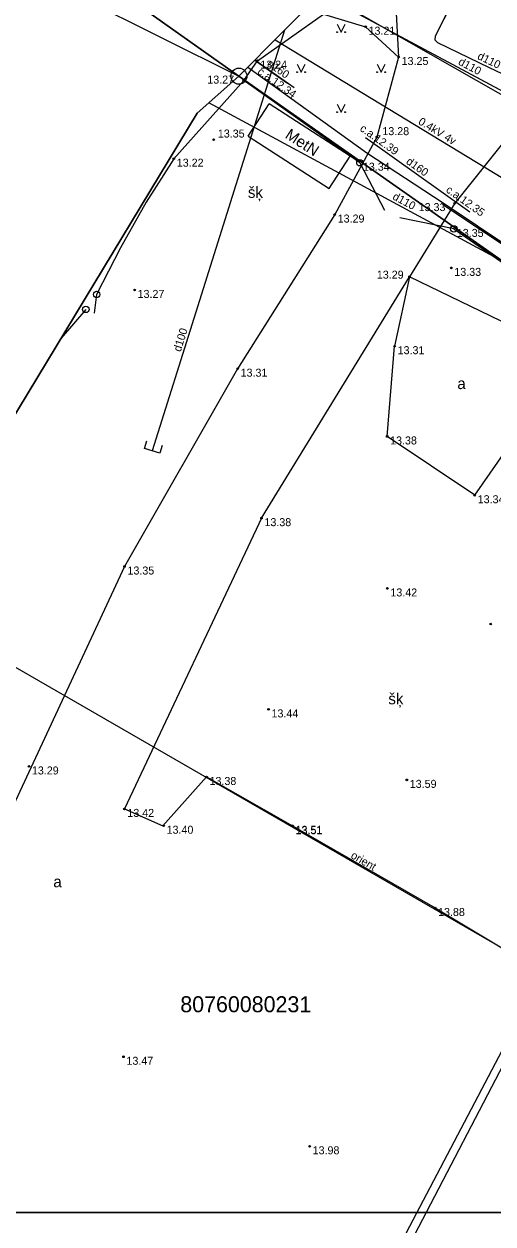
# Model space of a CAD drawing. Extents: x 503904 to 504094, y 304688 to 304960.
# Drawn here: x 503967.7 to 503997, y 304823 to 304898 of the extents above; entities that cross this region are included whole.
import ezdxf

# ---------------------------------------------------------------- set-up
doc = ezdxf.new("R2010")
doc.units = 0
for name, color, linetype in [('APGR_ELEM_####_####_#', 7, 'Continuous'), ('APGR_SARK_####_####_#', 7, 'Continuous'), ('APGS_ACRL_####_####_#', 7, 'Continuous'), ('APGS_ACRL_####_TKST_#', 7, 'Continuous'), ('APGS_VADP_ZSPR_####_#', 7, 'Continuous'), ('BUVE_EKAS_####_####_#', 7, 'Continuous'), ('BUVE_EKAS_BPAL_####_#', 7, 'Continuous'), ('BUVE_EKAS_RAKS_TKST_#', 7, 'Continuous'), ('CELI_CMAL_####_####_#', 7, 'Continuous'), ('CELI_CSEG_####_TKST_#', 7, 'Continuous'), ('CELI_TAKA_####_####_#', 7, 'Continuous'), ('ELEK_ACRL_####_####_#', 7, 'Continuous'), ('ELEK_ACRL_####_TKST_#', 7, 'Continuous'), ('ELEK_VADP_VSPR_####_#', 7, 'Continuous'), ('ELEK_VADP_VSPR_####_I', 7, 'Continuous'), ('ELEK_VADP_ZSPR_####_#', 7, 'Continuous'), ('ELEK_VADV_ZSPR_####_#', 7, 'Continuous'), ('ELEK_VADV_ZSPR_TKST_#', 7, 'Continuous'), ('NORB_ELEM_####_####_#', 7, 'Continuous'), ('NORB_ZOGS_BARJ_####_#', 7, 'Continuous'), ('NORB_ZOGS_ZSTP_####_#', 7, 'Continuous'), ('RAMI_PLAN_####_TKST_#', 7, 'Continuous'), ('RAMI_UZMR_####_####_#', 7, 'Continuous'), ('RELJ_AATZ_####_TKST_#', 7, 'Continuous'), ('RELJ_ELEM_####_####_#', 7, 'Continuous'), ('ROBZ_UZMR_####_####_#', 7, 'Continuous'), ('ROBZ_UZMR_####_TKST_#', 7, 'Continuous'), ('SAKK_KKAN_####_####_#', 7, 'Continuous'), ('SAKT_VADP_KABE_####_#', 7, 'Continuous'), ('SAKT_VADP_KABE_TKST_#', 7, 'Continuous'), ('TERT_ELEM_####_####_#', 7, 'Continuous'), ('UDTK_ELEM_####_####_#', 7, 'Continuous'), ('UDTK_VADP_NEDR_####_#', 7, 'Continuous'), ('UDTK_VADP_NEDR_TKST_#', 7, 'Continuous'), ('UDTK_VADP_UDEN_####_#', 7, 'Continuous'), ('UDTK_VADP_UDEN_TKST_#', 7, 'Continuous')]:
    doc.layers.add(name, color=color, linetype=linetype)

msp = doc.modelspace()

# ---------------------------------------------------------------- linework, layer by layer
at = {"layer": 'APGR_ELEM_####_####_#'}
msp.add_circle((503981.12, 304894.75), 0.5, dxfattribs=at)
at = {"layer": 'APGR_SARK_####_####_#'}
for p, q in [((503967.818, 304901.39), (503981.123, 304894.75)), ((503981.123, 304894.75), (504030.463, 304860.121))]:
    msp.add_line(p, q, dxfattribs=at)
at = {"layer": 'APGS_ACRL_####_####_#'}
msp.add_lwpolyline([(503997.708, 304905.8), (503994.46, 304899.393), (503993.378, 304897.257), (503993.361, 304897.025), (503993.516, 304896.851), (503996.758, 304895.298), (503998.379, 304894.525), (504000, 304893.745), (504003.241, 304892.193)], dxfattribs=at)
at = {"layer": 'APGS_VADP_ZSPR_####_#'}
msp.add_lwpolyline([(503994.396, 304908.162), (503998.01, 304906.396), (503995.543, 304901.529), (503993.378, 304897.257), (503993.361, 304897.025), (503993.516, 304896.85), (503996.758, 304895.3), (504000, 304893.749), (504004.081, 304891.797), (504008.162, 304889.845), (504008.322, 304889.653), (504008.281, 304889.406), (504007.328, 304888.005), (504006.375, 304886.604), (504006.058, 304885.968)], dxfattribs=at)
at = {"layer": 'BUVE_EKAS_####_####_#'}
msp.add_line((504000.528, 304838.553), (503966.985, 304774.25), dxfattribs=at)
at = {"layer": 'BUVE_EKAS_BPAL_####_#'}
for p, q in [((503981.706, 304891.005), (503983.013, 304893.018)), ((503988.061, 304889.741), (503983.013, 304893.018)), ((503981.706, 304891.005), (503986.754, 304887.728)), ((503986.754, 304887.728), (503988.061, 304889.741))]:
    msp.add_line(p, q, dxfattribs=at)
at = {"layer": 'CELI_CMAL_####_####_#'}
for points in [[(503988.454, 304902.158), (503990.823, 304901.054), (503991.097, 304895.946), (503989.732, 304890.943), (503987.103, 304886.103), (503981.039, 304876.47), (503973.971, 304864.108), (503962.412, 304839.295), (503956.935, 304827.255), (503950.616, 304813.727), (503945.51, 304803.343), (503951.501, 304800.629), (503951.721, 304801.18), (503956.987, 304798.767), (503955.478, 304795.066), (503959.037, 304792.215), (503963.727, 304789.581), (503971.677, 304784.658)], [(504004.157, 304894.141), (504000.966, 304892.903), (503997.999, 304891.059), (503994.598, 304886.807), (503991.776, 304882.213), (503990.847, 304877.876)], [(503982.528, 304867.129), (503991.776, 304882.213)], [(503995.849, 304868.561), (504001.94, 304877.298), (503991.776, 304882.213)], [(503990.378, 304872.235), (503990.847, 304877.876)], [(503995.849, 304868.561), (503990.378, 304872.235)], [(503982.528, 304867.129), (503973.963, 304848.96), (503976.364, 304847.909), (503979.097, 304850.955), (503984.468, 304847.903), (503993.374, 304842.768), (503998.697, 304839.581), (504000.143, 304838.769)], [(503980.391, 304801.145), (503991.362, 304822.043), (504000.143, 304838.769)]]:
    msp.add_lwpolyline(points, dxfattribs=at)
at = {"layer": 'CELI_TAKA_####_####_#'}
msp.add_lwpolyline([(503981.42, 304894.481), (503982.27, 304895.717), (503986.409, 304898.633), (503989.03, 304897.84), (503991.097, 304895.946)], dxfattribs=at)
at = {"layer": 'ELEK_ACRL_####_####_#'}
for points in [[(503986.232, 304899.912), (504002.69, 304891.089)], [(503984.572, 304894.017), (503982.115, 304895.752)], [(503989.021, 304890.917), (503995.535, 304886.272)]]:
    msp.add_lwpolyline(points, dxfattribs=at)
at = {"layer": 'ELEK_VADP_VSPR_####_#'}
msp.add_line((503999.944, 304882.63), (503993.832, 304886.735), dxfattribs=at)
msp.add_lwpolyline([(504017.859, 304874.234), (504017.356, 304874.141), (504010.022, 304879.253), (504006.684, 304878.224), (503993.887, 304886.818), (503989.112, 304889.931), (503981.666, 304895.299)], dxfattribs=at)
at = {"layer": 'ELEK_VADP_VSPR_####_I'}
msp.add_lwpolyline([(503982.105, 304895.742), (503983.04, 304895.08), (503984.146, 304894.318)], dxfattribs=at)
at = {"layer": 'ELEK_VADP_ZSPR_####_#'}
msp.add_lwpolyline([(503986.232, 304899.912), (504000, 304892.531), (504005.246, 304889.719), (504005.346, 304889.587), (504005.312, 304889.424), (504004.381, 304888.161)], dxfattribs=at)
at = {"layer": 'ELEK_VADV_ZSPR_####_#'}
msp.add_line((503983.376, 304897.026), (504001.595, 304885.938), dxfattribs=at)
at = {"layer": 'NORB_ELEM_####_####_#'}
for centre in [(503988.677, 304889.341), (503994.545, 304885.205), (503972.231, 304881.111), (503971.558, 304880.177)]:
    msp.add_circle(centre, 0.202, dxfattribs=at)
at = {"layer": 'NORB_ZOGS_BARJ_####_#'}
for p, q in [((503988.677, 304889.341), (503990.207, 304886.367)), ((503994.545, 304885.205), (503991.173, 304885.89)), ((503972.231, 304881.111), (503972.077, 304879.948))]:
    msp.add_line(p, q, dxfattribs=at)
at = {"layer": 'NORB_ZOGS_ZSTP_####_#'}
for points in [[(503988.677, 304889.341), (503981.42, 304894.481), (503977.05, 304889.593), (503975.315, 304886.879), (503973.711, 304884.013), (503972.231, 304881.111)], [(503994.545, 304885.205), (504006.615, 304876.836), (504018.641, 304868.474), (504030.525, 304860.01), (504021.686, 304844.338), (504014.326, 304831.324)], [(503971.558, 304880.177), (503970.014, 304878.368)]]:
    msp.add_lwpolyline(points, dxfattribs=at)
at = {"layer": 'RAMI_PLAN_####_TKST_#'}
for points in [[(503904.204, 304959.85), (504093.703, 304959.85), (504093.703, 304823.741), (503904.204, 304823.741)], [(503904.204, 304823.741), (504093.703, 304823.741), (504093.703, 304687.633), (503904.204, 304687.633)]]:
    msp.add_lwpolyline(points, close=True, dxfattribs=at)
at = {"layer": 'RAMI_UZMR_####_####_#'}
msp.add_lwpolyline([(503923.253, 304801.015), (503981.982, 304759.672), (503995.48, 304748.813), (504027.75, 304817.255), (504060.02, 304885.696), (504048.875, 304885.773), (504036.803, 304888.853), (503994.536, 304908.303), (503981.123, 304894.75), (503978.518, 304892.436), (503950.886, 304846.726), (503923.253, 304801.015)], dxfattribs=at)
at = {"layer": 'RELJ_ELEM_####_####_#'}
for centre in [(503989.03, 304897.84), (503982.27, 304895.717), (503991.097, 304895.946), (503981.42, 304894.481), (503979.54, 304890.778), (503989.732, 304890.943), (503977.05, 304889.593), (503994.598, 304886.807), (503987.103, 304886.103), (503991.776, 304882.213), (503994.39, 304882.77), (503974.604, 304881.392), (503990.847, 304877.876), (503981.039, 304876.47), (503990.378, 304872.235), (503995.849, 304868.561), (503982.528, 304867.129), (503973.971, 304864.108), (503990.395, 304862.737), (503996.847, 304860.512), (503982.969, 304855.178), (503968.001, 304851.614), (503979.097, 304850.955), (503991.605, 304850.774), (503973.963, 304848.96), (503976.414, 304847.909), (503984.468, 304847.903), (503984.477, 304847.874), (503993.374, 304842.768), (503973.907, 304833.47), (503985.538, 304827.876)]:
    msp.add_circle(centre, 0.05, dxfattribs=at)
at = {"layer": 'ROBZ_UZMR_####_####_#'}
for points in [[(504052.953, 304844.812), (504048.85, 304847.4), (504030.463, 304860.121), (503981.123, 304894.75), (503968.011, 304904.031)], [(503968.744, 304903.512), (503981.123, 304894.75), (503978.518, 304892.436), (503923.29, 304801.044), (503917.762, 304804.94)]]:
    msp.add_lwpolyline(points, dxfattribs=at)
msp.add_lwpolyline([(503923.29, 304801.044), (503978.518, 304892.436), (503981.123, 304894.75), (504030.463, 304860.121), (503981.982, 304759.672)], close=True, dxfattribs=at)
at = {"layer": 'SAKK_KKAN_####_####_#'}
msp.add_lwpolyline([(503986.316, 304899.997), (504000, 304892.196), (504013.782, 304884.178), (504021.554, 304879.802), (504033.218, 304873.459), (504039.007, 304870.064), (504043.395, 304867.859), (504047.782, 304865.655), (504048.401, 304866.822), (504050.758, 304867.21)], dxfattribs=at)
at = {"layer": 'SAKT_VADP_KABE_####_#'}
msp.add_lwpolyline([(504000.528, 304838.553), (503960.08, 304861.879)], dxfattribs=at)
at = {"layer": 'TERT_ELEM_####_####_#'}
for p, q in [((503987.25, 304898), (503987.5, 304897.5)), ((503987.5, 304897.5), (503987.75, 304898)), ((503984.75, 304895.5), (503985, 304895)), ((503985, 304895), (503985.25, 304895.5)), ((503989.75, 304895.5), (503990, 304895)), ((503990, 304895), (503990.25, 304895.5)), ((503987.25, 304893), (503987.5, 304892.5)), ((503987.5, 304892.5), (503987.75, 304893))]:
    msp.add_line(p, q, dxfattribs=at)
for centre, radius in [((503987.25, 304897.5), 0.028), ((503987.75, 304897.5), 0.0263), ((503984.75, 304895), 0.028), ((503985.25, 304895), 0.0263), ((503989.75, 304895), 0.028), ((503990.25, 304895), 0.0263), ((503987.25, 304892.5), 0.028), ((503987.75, 304892.5), 0.0263)]:
    msp.add_circle(centre, radius, dxfattribs=at)
at = {"layer": 'UDTK_ELEM_####_####_#'}
msp.add_lwpolyline([(503976.325, 304871.668), (503976.174, 304871.191), (503975.221, 304871.491), (503975.371, 304871.968)], dxfattribs=at)
at = {"layer": 'UDTK_VADP_NEDR_####_#'}
msp.add_lwpolyline([(503983.969, 304897.625), (503981.155, 304888.683), (503978.426, 304880.012), (503975.698, 304871.341)], dxfattribs=at)
at = {"layer": 'UDTK_VADP_UDEN_####_#'}
msp.add_lwpolyline([(504035.876, 304862.497), (503979.246, 304893.082)], dxfattribs=at)

# ---------------------------------------------------------------- texts
at = {"layer": 'APGS_ACRL_####_TKST_#'}
msp.add_text('d110', height=0.5, rotation=334.40496, dxfattribs=at).set_placement((503995.971, 304895.841))
at = {"layer": 'BUVE_EKAS_RAKS_TKST_#'}
msp.add_text('MetN', height=0.7, rotation=327.00966, dxfattribs=at).set_placement((503983.95, 304890.931))
at = {"layer": 'CELI_CSEG_####_TKST_#'}
for s, p in [('šķ', (503981.681, 304887.145)), ('a', (503994.766, 304875.195)), ('šķ', (503990.455, 304855.496)), ('a', (503969.526, 304844.064))]:
    msp.add_text(s, height=0.7, dxfattribs=at).set_placement(p)
at = {"layer": 'ELEK_ACRL_####_TKST_#'}
for s, rotation, p in [('d160', 324.76768, (503982.83, 304895.431)), ('d110', 331.80396, (503994.776, 304895.502)), ('c.a.12.34', 324.76768, (503982.232, 304894.935)), ('c.a.12.39', 324.51021, (503988.63, 304891.38)), ('d160', 324.51021, (503991.519, 304889.32)), ('c.a.12.35', 324.51021, (503994.007, 304887.547))]:
    msp.add_text(s, height=0.5, rotation=rotation, dxfattribs=at).set_placement(p)
at = {"layer": 'ELEK_VADV_ZSPR_TKST_#'}
msp.add_text('0.4kV 4v', height=0.5, rotation=328.67676, dxfattribs=at).set_placement((503992.277, 304891.784))
at = {"layer": 'RELJ_AATZ_####_TKST_#'}
for s, p in [(' 13.21', (503989.03, 304897.34)), (' 13.25', (503991.097, 304895.446)), (' 13.24', (503982.27, 304895.217)), (' 13.27', (503978.958, 304894.286)), (' 13.35', (503979.617, 304890.914)), (' 13.28', (503989.894, 304891.064)), (' 13.22', (503977.05, 304889.093)), (' 13.34', (503988.677, 304888.841)), (' 13.33', (503992.163, 304886.318)), (' 13.29', (503987.103, 304885.603)), (' 13.35', (503994.545, 304884.705)), (' 13.29', (503989.549, 304882.096)), (' 13.33', (503994.39, 304882.27)), (' 13.27', (503974.604, 304880.892)), (' 13.31', (503990.847, 304877.376)), (' 13.31', (503981.039, 304875.97)), (' 13.38', (503990.378, 304871.735)), (' 13.34', (503995.849, 304868.061)), (' 13.38', (503982.528, 304866.629)), (' 13.35', (503973.971, 304863.608)), (' 13.42', (503990.395, 304862.237)), (' 13.44', (503982.969, 304854.678)), (' 13.29', (503968.001, 304851.114)), (' 13.38', (503979.097, 304850.455)), (' 13.59', (503991.605, 304850.274)), (' 13.42', (503973.963, 304848.46)), (' 13.40', (503976.414, 304847.409)), (' 13.51', (503984.468, 304847.403)), (' 13.51', (503984.477, 304847.374)), (' 13.88', (503993.374, 304842.268)), (' 13.47', (503973.907, 304832.97)), (' 13.98', (503985.538, 304827.376))]:
    msp.add_text(s, height=0.5, dxfattribs=at).set_placement(p)
at = {"layer": 'ROBZ_UZMR_####_TKST_#'}
msp.add_text('80760080231', height=1, dxfattribs=at).set_placement((503977.456, 304836.253))
at = {"layer": 'SAKT_VADP_KABE_TKST_#'}
msp.add_text('orient', height=0.5, rotation=330.02905, dxfattribs=at).set_placement((503988.061, 304845.916))
at = {"layer": 'UDTK_VADP_NEDR_TKST_#'}
msp.add_text('d100', height=0.5, rotation=72.53259, dxfattribs=at).set_placement((503977.476, 304877.492))
at = {"layer": 'UDTK_VADP_UDEN_TKST_#'}
msp.add_text('d110', height=0.5, rotation=331.62708, dxfattribs=at).set_placement((503990.674, 304887.081))

doc.saveas('drawing.dxf')
